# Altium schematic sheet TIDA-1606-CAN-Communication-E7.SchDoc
size A3; Date: Not shown in title block; ApprovedBy: Not shown in title block; CheckedBy: Not shown in title block; Author: Not shown in title block; CompanyName: Not shown in title block; Engineer: Not shown in title block; Organization: Not shown in title block; Address1: Not shown in title block; Address2: Not shown in title block; Address3: Not shown in title block; Address4: Not shown in title block; DocumentNumber: 15; Revision: Use project parameter SCH_Rev; SheetNumber: 15; SheetTotal: 16; PageSetup: Record=PageOptions¦CenterHorizontal=True¦CenterVertical=True¦PrintScale=0.69¦XCorrection=1.00¦YCorrection=1.00¦PrintKind=0¦BorderSize=5000000¦LeftOffset=0¦BottomOffset=0¦Orientation=2¦PaperLength=1000¦PaperWidth=1000¦Scale=100¦PaperSource=15¦PrintQuality=600¦MediaType=1¦DitherType=10¦PaperKind=Letter¦PrintScaleMode=1
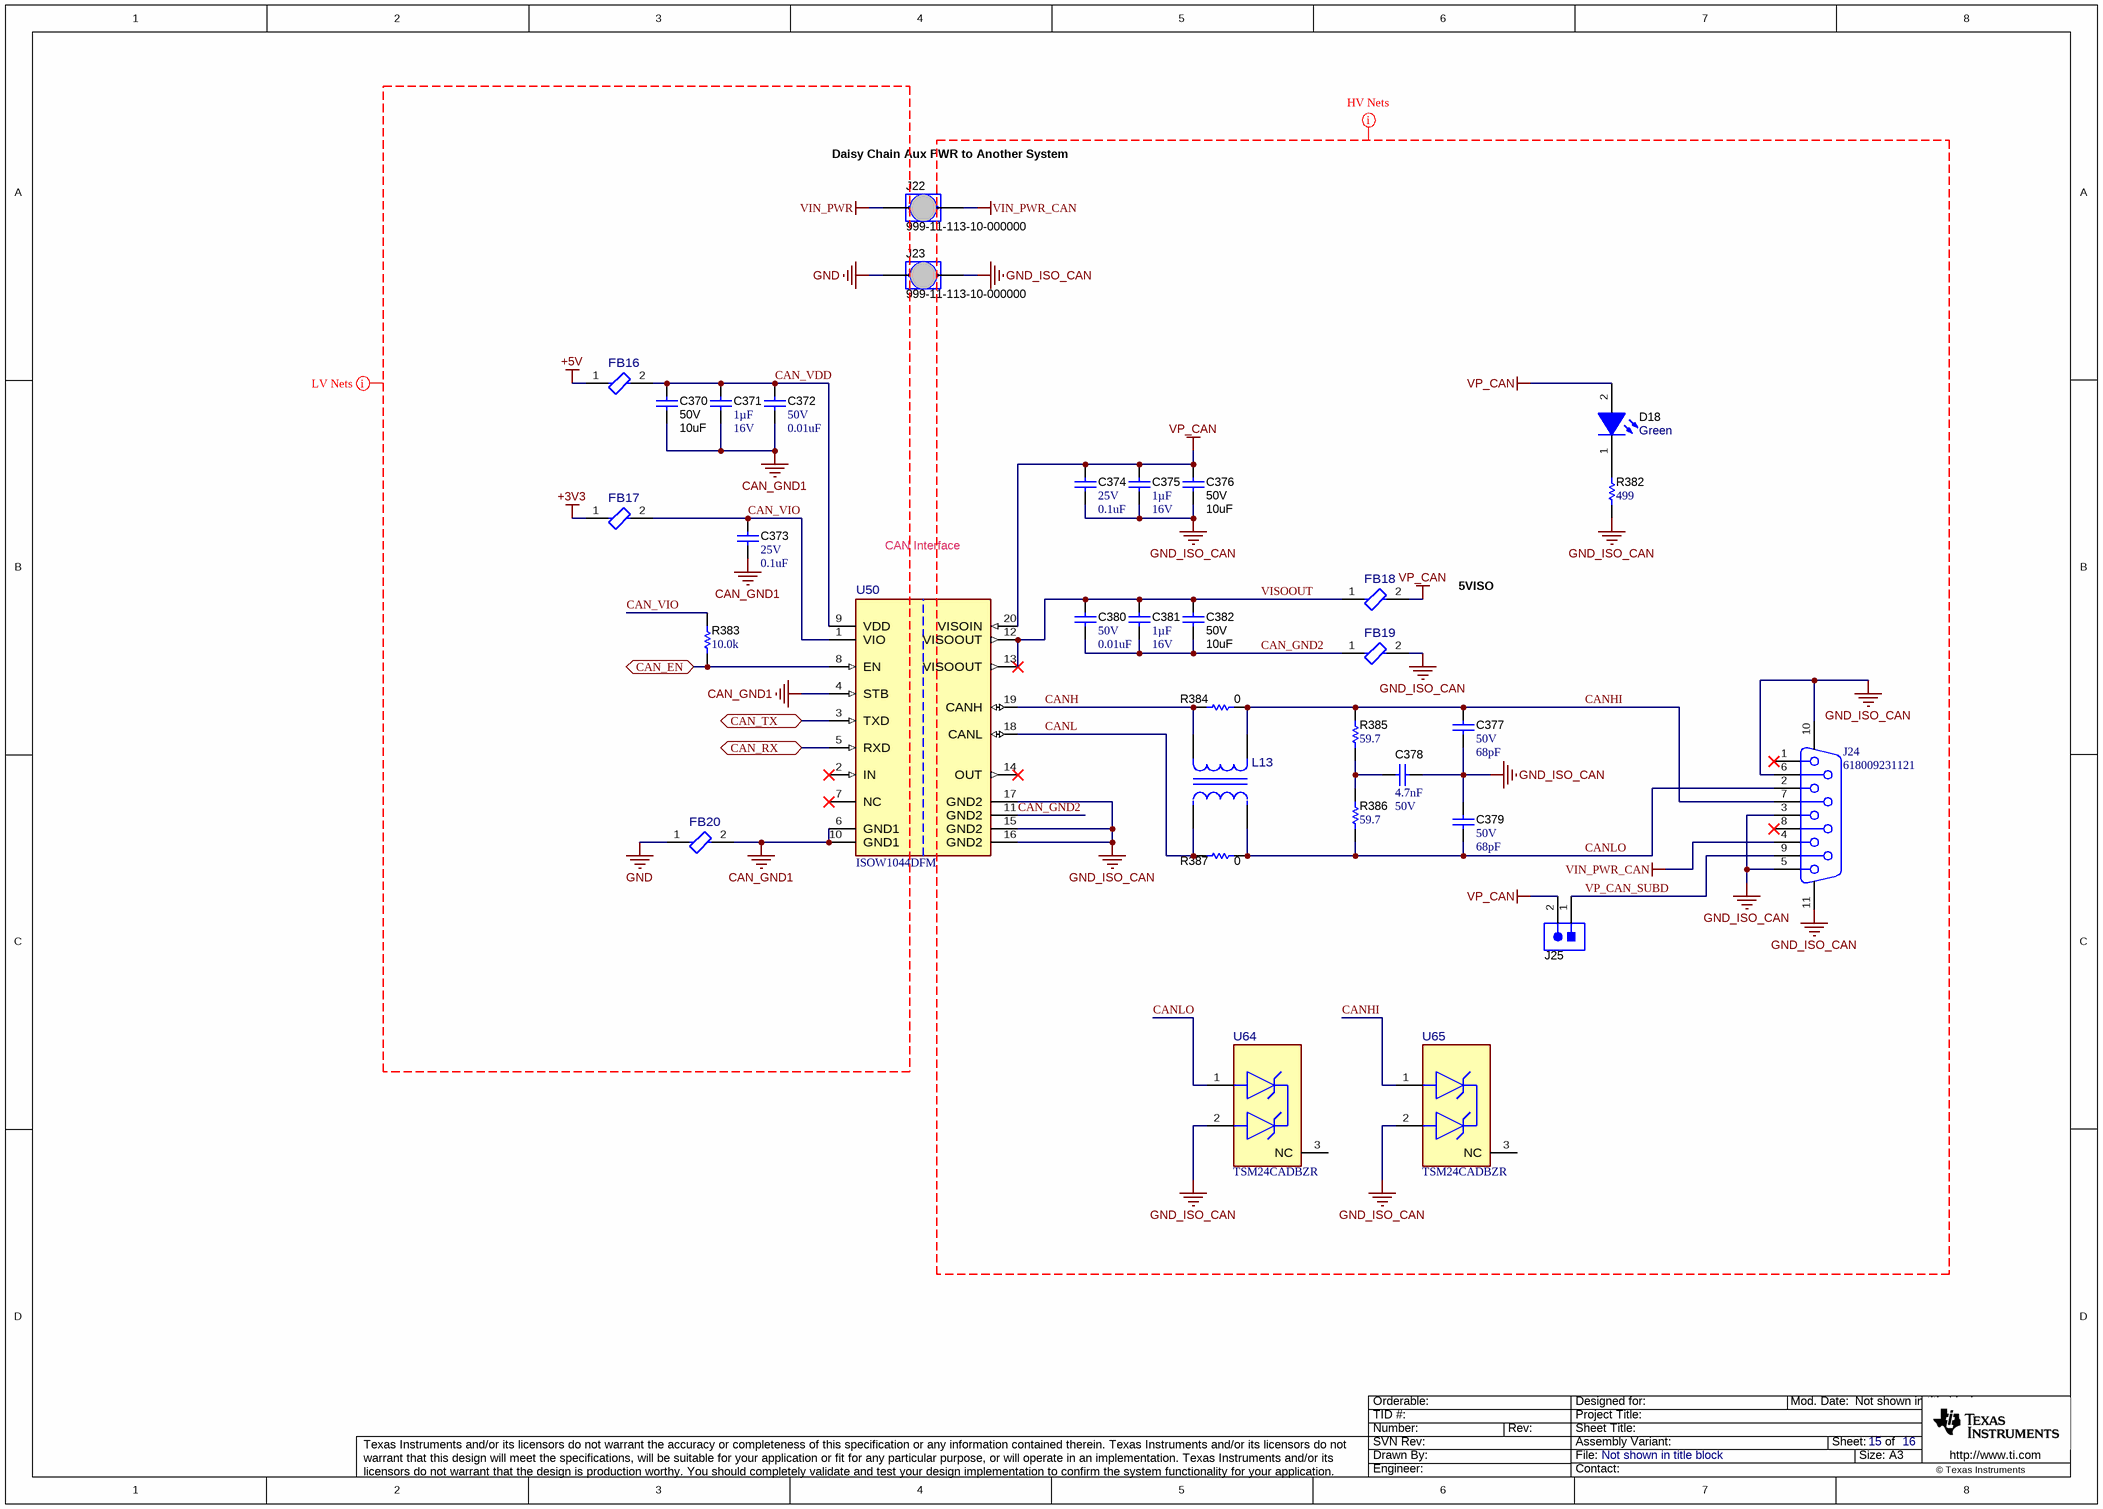
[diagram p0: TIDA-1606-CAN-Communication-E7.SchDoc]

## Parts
C370  VDC_V: 50V  ValueDisplayed: 10uF  [1206_180L]  (hidden comment: CL31B106KBHNNNE)
C371  Cap_F: 1µF  VDC_V: 16V  [0603]  (hidden comment: GCM188R71C105KA64J)
C372  VDC_V: 50V  ValueDisplayed: 0.01uF  [0402]  (hidden comment: GRM155R71H103KA88D)
C373  VDC_V: 25V  ValueDisplayed: 0.1uF  [0402]  (hidden comment: GRM155R71E104KE14D)
C374  VDC_V: 25V  ValueDisplayed: 0.1uF  [0402]  (hidden comment: GRM155R71E104KE14D)
C375  Cap_F: 1µF  VDC_V: 16V  [0603]  (hidden comment: GCM188R71C105KA64J)
C376  VDC_V: 50V  ValueDisplayed: 10uF  [1206_180L]  (hidden comment: CL31B106KBHNNNE)
C377  VDC_V: 50V  ValueDisplayed: 68pF  [0402]  (hidden comment: C1005C0G1H680J050BA)
C378  Cap_F: 4.7nF  VDC_V: 50V  [0603]  (hidden comment: C0603X472K5RACTU)
C379  VDC_V: 50V  ValueDisplayed: 68pF  [0402]  (hidden comment: C1005C0G1H680J050BA)
C380  VDC_V: 50V  ValueDisplayed: 0.01uF  [0402]  (hidden comment: GRM155R71H103KA88D)
C381  Cap_F: 1µF  VDC_V: 16V  [0603]  (hidden comment: GCM188R71C105KA64J)
C382  VDC_V: 50V  ValueDisplayed: 10uF  [1206_180L]  (hidden comment: CL31B106KBHNNNE)
D18  value Green  [WL-SMCW_GREEN]  (hidden comment: 150060VS75000)
FB16  BLM15EX331SN1D  [FP-BLM15EX331SN1D_0402-MFG]  (value not drawn)
FB17  BLM15EX331SN1D  [FP-BLM15EX331SN1D_0402-MFG]  (value not drawn)
FB18  BLM15EX331SN1D  [FP-BLM15EX331SN1D_0402-MFG]  (value not drawn)
FB19  BLM15EX331SN1D  [FP-BLM15EX331SN1D_0402-MFG]  (value not drawn)
FB20  BLM15EX331SN1D  [FP-BLM15EX331SN1D_0402-MFG]  (value not drawn)
J22  999-11-113-10-000000  [Mill-Max_999-11-113-10-000000]
J23  999-11-113-10-000000  [Mill-Max_999-11-113-10-000000]
J24  618009231121  [Wurth_618009231121]
J25  61300211121  [WURTH_61300211121]  (value not drawn)
L13  ACT45B-101-2P-TL003  [FP-ACT45B-101-2P-TL003_SMT_4MM5_3MM2-MFG]  (value not drawn)
R382  ValueDisplayed: 499  [0603]  (hidden comment: CRCW0603499RFKEAC)
R383  ValueDisplayed: 10.0k  [0402]  (hidden comment: CRCW040210K0FKED)
R384  ValueDisplayed: 0  [0603]  (hidden comment: RCS06030000Z0EA)
R385  ValueDisplayed: 59.7  [0603]  (hidden comment: RT0603DRE0759R7L)
R386  ValueDisplayed: 59.7  [0603]  (hidden comment: RT0603DRE0759R7L)
R387  ValueDisplayed: 0  [0603]  (hidden comment: RCS06030000Z0EA)
U50  ISOW1044DFM  [DFM0020A-MFG]
U64  TSM24CADBZR  [DBZ0003A-MFG]
U65  TSM24CADBZR  [DBZ0003A-MFG]

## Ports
CAN_EN (bidir), CAN_RX (bidir), CAN_TX (bidir)

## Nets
+3V3: FB17.1
+5V: FB16.1
CAN_GND1: C370.2 C371.2 C372.2 C373.2 FB20.2 U50.4(STB) U50.6(GND1) U50.10(GND1)
GND: FB20.1 J23.1
GND_ISO_CAN: C374.2 C375.2 C376.2 C377.2 C378.1 C379.1 FB19.2 J23.2 J24.3 J24.5 J24.6 J24.10 J24.11 R382.1 U50.15(GND2) U50.16(GND2) U50.17(GND2) U64.2(2_IO) U65.2(2_IO)
VIN_PWR: J22.1
VIN_PWR_CAN: J22.2 J24.4
VP_CAN: C374.1 C375.1 C376.1 D18.2(A) FB18.2 J25.2 U50.20(VISOIN)
CAN_EN: R383.1 U50.8(EN) ; port CAN_EN
CAN_GND2: C380.2 C381.2 C382.2 FB19.1 U50.11(GND2)
CAN_RX: U50.5(RXD) ; port CAN_RX
CAN_TX: U50.3(TXD) ; port CAN_TX
CAN_VDD: C370.1 C371.1 C372.1 FB16.2 U50.9(VDD)
CAN_VIO: C373.1 FB17.2 R383.2 U50.1(VIO)
CANH: L13.1 R384.2 U50.19(CANH)
CANHI: C377.1 J24.7 L13.4 R384.1 R385.2 U65.1(1_IO)
CANL: L13.2 R387.2 U50.18(CANL)
CANLO: C379.2 J24.2 L13.3 R386.1 R387.1 U64.1(1_IO)
VISOOUT: C380.1 C381.1 C382.1 FB18.1 U50.12(VISOOUT) U50.13(VISOOUT)
VP_CAN_SUBD: J24.9 J25.1
NetC378_2: C378.2 R385.1 R386.2
NetD18_1: D18.1(K) R382.2

Not connected (* = marked no-connect by the designer): J24 1* 8*; U50 2(IN)* 7(NC)* 14(OUT)*; U64 3(NC); U65 3(NC)

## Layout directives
net class HV_Nets; net class HV_CAN: CAN_GND2, CANH, CANHI, CANL, CANLO, GND_ISO_CAN, VIN_PWR_CAN, VISOOUT, VP_CAN, VP_CAN_SUBD
net class LV Nets: +3V3, +5V, CAN_GND1, CAN_VDD, CAN_VIO, GND, VIN_PWR

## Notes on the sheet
- (near J22) Daisy Chain Aux PWR to Another System
- CAN Interface
- 5VISO

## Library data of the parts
C370 C376 C382 = CMP-0008802-2: CAP, CERM, 10 uF, 50 V, +/- 10%, X7R, 1206; Manufacturer: Samsung; TaMin_C: -55°C; Polarized: N; SizeAreaWB_mm2: 10.92; Value1: Unknown; U/M: EA; Value: 10uF; TaMax_C: 125°C; SizeZ_mm: 1.8; SizeX_mm: 3.2; SizeY_mm: 1.6; Cap_Case: 1206; SizeArea_mm2: 5.12; Cap_F: 10µF; AEC Category: Q200
C371 C375 C381 = CMP-0079154-1: CAP, CERM, 1 µF, 16 V,+/- 10%, X7R, AEC-Q200 Grade 1, 0603; Manufacturer: MuRata; SizeAreaWB_mm2: 4.68; SizeArea_mm2: 1.28; AEC Qualified: Y; AEC Category: Q200; Value: 1uF; TaMax_C: 125°C; SizeZ_mm: 1; Polarized: N; TaMin_C: -55°C; SizeY_mm: 0.8; U/M: EA; SizeX_mm: 1.6
C372 C380 = CMP-0006674-2: CAP, CERM, 0.01 uF, 50 V, +/- 10%, X7R, 0402; Manufacturer: MuRata; TaMin_C: -55°C; Polarized: N; SizeAreaWB_mm2: 3; Value1: Unknown; U/M: EA; Value: 0.01uF; TaMax_C: 125°C; SizeZ_mm: 0.6; SizeX_mm: 1; SizeY_mm: 0.5; Cap_F: 10nF; AEC Category: Q200
C373 C374 = CMP-0006659-2: CAP, CERM, 0.1 uF, 25 V, +/- 10%, X7R, 0402; Manufacturer: MuRata; TaMin_C: -55°C; Polarized: N; SizeAreaWB_mm2: 3; Value1: Unknown; U/M: EA; Value: 0.1uF; TaMax_C: 125°C; SizeZ_mm: 0.6; SizeX_mm: 1; SizeY_mm: 0.5; Cap_F: 100nF; AEC Category: Q200
C377 C379 = CMP-0006251-2: CAP, CERM, 68 pF, 50 V, +/- 5%, C0G/NP0, 0402; Manufacturer: TDK; TaMin_C: -55°C; Polarized: N; SizeAreaWB_mm2: 3; Value1: Unknown; U/M: EA; Value: 68pF; TaMax_C: 125°C; SizeZ_mm: 0.6; SizeX_mm: 1; SizeY_mm: 0.5; AEC Category: Q200
C378 = CMP-0006987-4: CAP, CERM, 4700 pF, 50 V, +/- 10%, X7R, 0603; Manufacturer: Kemet; TaMin_C: -55°C; Polarized: N; SizeAreaWB_mm2: 4.68; Value1: Unknown; U/M: EA; Value: 4700pF; TaMax_C: 125°C; SizeZ_mm: 1; SizeX_mm: 1.6; SizeY_mm: 0.8; SizeArea_mm2: 1.28; AEC Category: Q200
D18 = CMP-0002894-2: LED, Green, SMD; Manufacturer: Wurth Elektronik; Type: AlInGaP; Value2: 2V; Io_A: 20mA; Value1: W
FB16-FB20 = CMP-0041881-1: Chip Ferrite Bead, 0402, 330Ω @ 100MHz, 0.205Ω, 25%, 1.1A; Manufacturer: Murata; DCR_ohm: 0.205; SizeZ_mm: 0.55mm; AEC Qualified: No; Ciiva Ids: 2806665; Import Ts: 1521856324
J22 J23 = CMP-0055045-1: Shorting Jumper, 7.62mm, 2 Position, Gold, TH; Manufacturer: Mill-Max; CNHeader: FALSE; Gender: Male; Pitch_mm: 7.62; Cert_UL: Y
J24 = CMP-0054820-2: Receptacle, D-Sub, 9 Position, R/A, TH; Manufacturer: Wurth Elektronik; Pitch_mm: 2.77; Gender: Female; Cert_UL: Y; Voltage_V: 125V; ContactFinish: Gold; Row_Count: 2; Current_A: 3A; CNHeader: FALSE; CT: TRUE
J25 = CMP-0054794-2: Header, 2.54 mm, 2x1, Gold, TH; Manufacturer: Wurth Elektronik; Green_Lifecycle: Active; Green_REACh: Passed; Cert_UL: Y; Gender: Male; Pitch_mm: 2.54; Row_Count: 1; Shrouded: N
L13 = CMP-0084086-1: 100µH @ 100kHz 2 Line Common Mode Choke Surface Mount 5.8 kOhms @ 10MHz 150mA DCR 2Ohm; Manufacturer: TDK; AEC Grade: Grade 0; Tolerance_%: +50/-30%; AEC Qualified: Yes; Ind_H: 100uH; SizeZ_mm: 3mm; DCR_ohm: 2Ω; Impedance At Frequency: 5800Ω @ 10MHz; Imax_A: 0.15A
R382 = CMP-0082532-1: RES, 499, 1%, 0.1 W, 0603; Manufacturer: Vishay-Dale; Power_W: 100mW; TempCo: 100 ppm/C; SizeAreaWB_mm2: 4.68; Value_Code: 499R; Value: 499; EIA_Code: E96; SizeX_mm: 1.6; SizeY_mm: 0.8; SizeZ_mm: 1; Value2: 0.1W; SizeArea_mm2: 1.28; AEC Qualified: N; VDC_V: 75V; AEC Category: Q200
R383 = CMP-0025958-3: RES, 10.0 k, 1%, 0.063 W, AEC-Q200 Grade 0, 0402; Manufacturer: Vishay-Dale; Power_W: 63mW; TempCo: 100 ppm/C; Value_Code: 10k0; Value: 10.0k; EIA_Code: E96; Res_ohm: 10k; SizeX_mm: 1; SizeY_mm: 0.5; SizeZ_mm: 0.6; Value2: 0.063W; AEC Qualified: Y; VDC_V: 50V; AEC Category: Q200; AEC Grade: 0
R384 R387 = CMP-0081973-1: RES, 0, 0%, 0.25 W, AEC-Q200 Grade 0, 0603; Manufacturer: Vishay-Dale; SizeAreaWB_mm2: 4.68; SizeArea_mm2: 1.28; AEC Qualified: Y; AEC Category: Q200; Value: 0; SizeZ_mm: 1; SizeY_mm: 0.8; Power_W: 250mW; Value2: 0.25W; SizeX_mm: 1.6
R385 R386 = CMP-0025431-3: RES, 59.7, 0.5%, 0.1 W, 0603; Manufacturer: Yageo America; Power_W: 100mW; TempCo: 50 ppm/C; Value_Code: 59R7; U/M: EA; Value: 59.7; EIA_Code: E192; SizeX_mm: 1.6; SizeY_mm: 0.8; SizeZ_mm: 1; Value2: 0.1W; SizeArea_mm2: 1.28; VDC_V: 75V; AEC Category: Q200
U50 = CMP-0092023-2: Reinforced 5-kVRMS Isolated CAN Transceiver with Integrated lowemissions DC-DC Converter; Manufacturer: Texas Instruments; TJmax_C: +150°C; Max Supply Voltage: 5.5V; AEC Qualified: No; Standoff Height: 0.1mm; Nominal Supply Current: 0.3-124mA; CompType: IC; AEC Category: Q200; TaMax_C: +105°C; SizeZ_mm: 3.55mm; Min Supply Voltage: 1.71V; TaMin_C: -40°C
U64 U65 = CMP-0120116-1: ±24 V Low Capacitance Surge Diode for Industrial Networks in SOT-23 Package; Manufacturer: Texas Instruments; SizeZ_mm: 1.12mm; AEC Qualified: No; Breakdown Voltage: 25.5V; Cap_F: 14pF; Clamping Voltage: 35V; Direction: Bidirectional; Ipp: 30A; Number Of Channels: 1; Ppk: 1200W; Standoff Height: 0.01mm; TaMax_C: +125°C; TaMin_C: -40°C; VRWM: 24V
